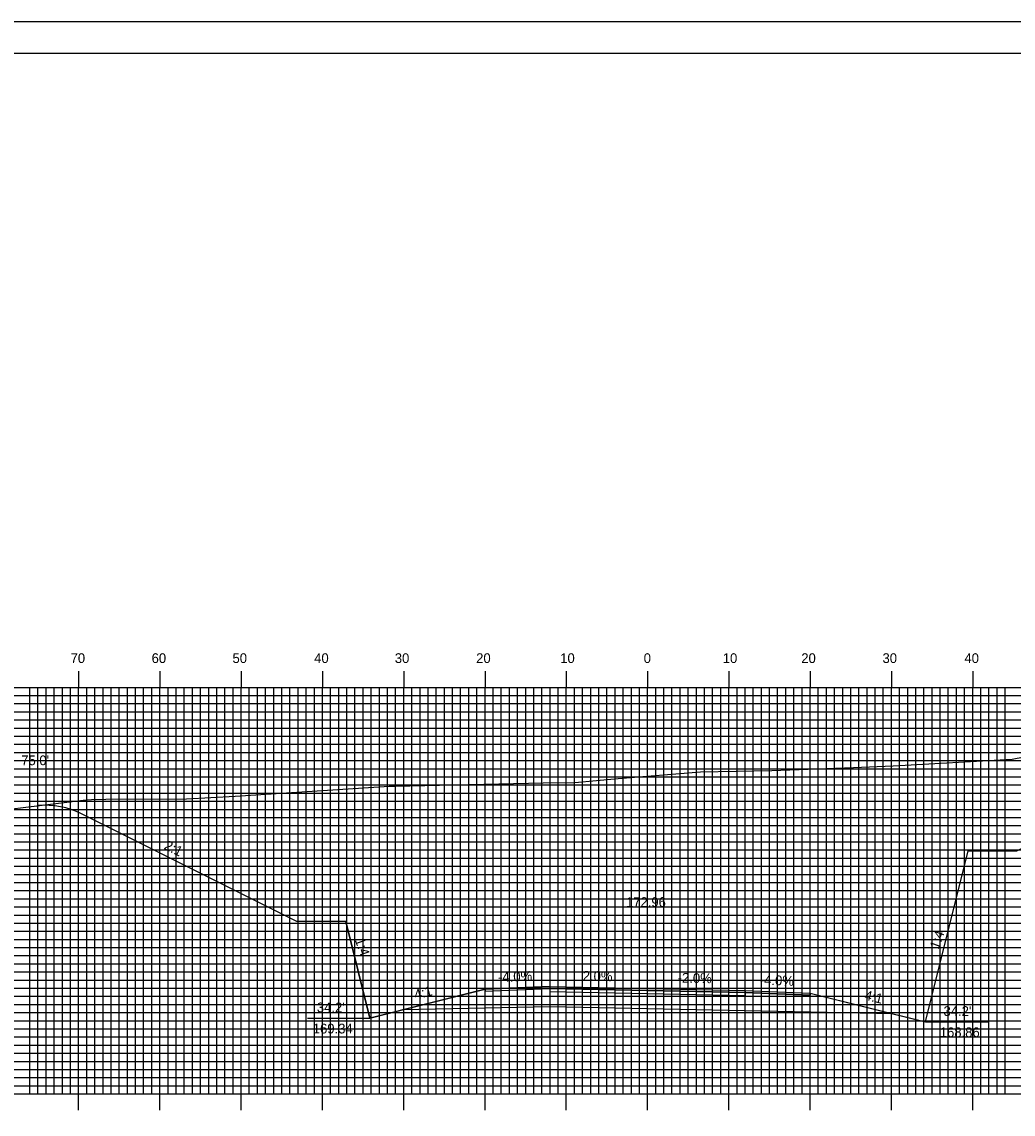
# Model space of a CAD drawing. Extents: x 1794846 to 1795189, y 442591 to 442811.
# Drawn here: x 1794934.9 to 1795056.8, y 442676.2 to 442810.5 of the extents above; entities that cross this region are included whole.
import ezdxf

# ---------------------------------------------------------------- set-up
doc = ezdxf.new("R2010")
doc.units = 0
for name, color, linetype in [('ANNOTATION', 7, 'Continuous'), ('BORDER', 7, 'Continuous'), ('D_Roadway_Centerline', 7, 'Continuous'), ('D_Roadway_Centerline_Text', 7, 'Continuous'), ('D_Roadway_Edge_Shoulder', 7, 'Continuous'), ('D_Roadway_Edge_TW', 7, 'Continuous'), ('D_Roadway_Pavement', 7, 'Continuous'), ('D_Roadway_SlopeLines', 7, 'Continuous'), ('D_Roadway_SubGrade', 7, 'Continuous'), ('D_Text_Standard', 7, 'Continuous'), ('H_V ANNOTATION', 7, 'Continuous'), ('MAJOR', 7, 'Continuous'), ('MINOR', 7, 'Continuous'), ('PDRAIN', 7, 'Continuous'), ('PLOT BOUNDARY', 7, 'Continuous'), ('S_Roadway_Centerline', 7, 'Continuous')]:
    doc.layers.add(name, color=color, linetype=linetype)

msp = doc.modelspace()

# ---------------------------------------------------------------- linework, layer by layer
at = {"layer": 'BORDER'}
msp.add_lwpolyline([(1794862.25, 442596.67), (1795182.25, 442596.67), (1795182.25, 442806.67), (1794862.25, 442806.67)], close=True, dxfattribs=at)
at = {"layer": 'D_Roadway_Centerline'}
msp.add_lwpolyline([(1794974.71, 442699.87), (1794977.68, 442688), (1794981.68, 442689), (1794991.85, 442691.55), (1794999.85, 442691.87), (1795011.85, 442691.63), (1795023.85, 442691.39), (1795031.85, 442691.07), (1795042.03, 442688.52), (1795046.03, 442687.52), (1795051.29, 442708.57), (1795057.29, 442708.57), (1795081.65, 442720.74)], dxfattribs=at)
msp.add_arc((1794937.74, 442704.17), 10, 63.4349, 95.1256, dxfattribs=at)
at = {"layer": 'D_Roadway_Edge_Shoulder'}
for points in [[(1794999.85, 442691.87), (1794991.85, 442691.55), (1794991.85, 442691.3), (1794999.85, 442691.62)], [(1795023.85, 442691.39), (1795031.85, 442691.07), (1795031.85, 442690.82), (1795023.85, 442691.14)]]:
    msp.add_lwpolyline(points, close=True, dxfattribs=at)
at = {"layer": 'D_Roadway_Edge_TW'}
msp.add_lwpolyline([(1794999.85, 442691.62), (1794999.85, 442691.87), (1795011.85, 442691.63), (1795023.85, 442691.39), (1795023.85, 442691.14), (1795011.85, 442691.38)], close=True, dxfattribs=at)
at = {"layer": 'D_Roadway_Pavement'}
msp.add_lwpolyline([(1794999.85, 442691.2), (1794999.85, 442691.62), (1795011.85, 442691.38), (1795023.85, 442691.14), (1795023.85, 442690.72), (1795011.85, 442690.96)], close=True, dxfattribs=at)
at = {"layer": 'D_Roadway_SlopeLines'}
for points in [[(1794974.71, 442699.87), (1794968.71, 442699.87), (1794942.22, 442713.11)], [(1794977.68, 442688), (1794974.71, 442699.87)], [(1794991.85, 442691.55), (1794977.68, 442688)], [(1795031.85, 442691.07), (1795046.03, 442687.52)]]:
    msp.add_lwpolyline(points, dxfattribs=at)
at = {"layer": 'D_Roadway_SubGrade'}
msp.add_lwpolyline([(1794999.85, 442689.37), (1794981.68, 442689), (1794991.85, 442691.55), (1794991.85, 442691.3), (1794999.85, 442691.62), (1795011.85, 442691.38), (1795023.85, 442691.14), (1795031.85, 442690.82), (1795031.85, 442691.07), (1795042.03, 442688.52), (1795023.85, 442688.89), (1795011.85, 442689.13)], close=True, dxfattribs=at)
at = {"layer": 'MAJOR'}
for p, q in [((1794941.85, 442730.67), (1794941.85, 442728.67)), ((1794951.85, 442730.67), (1794951.85, 442728.67)), ((1794961.85, 442730.67), (1794961.85, 442728.67)), ((1794971.85, 442730.67), (1794971.85, 442728.67)), ((1794981.85, 442730.67), (1794981.85, 442728.67)), ((1794991.85, 442730.67), (1794991.85, 442728.67)), ((1795001.85, 442730.67), (1795001.85, 442728.67)), ((1795011.85, 442730.67), (1795011.85, 442728.67)), ((1795021.85, 442730.67), (1795021.85, 442728.67)), ((1795031.85, 442730.67), (1795031.85, 442728.67)), ((1795041.85, 442730.67), (1795041.85, 442728.67)), ((1795051.85, 442730.67), (1795051.85, 442728.67)), ((1794871.85, 442728.67), (1795151.85, 442728.67)), ((1794871.85, 442728.67), (1795151.85, 442728.67)), ((1794941.85, 442678.67), (1794941.85, 442728.67)), ((1794951.85, 442678.67), (1794951.85, 442728.67)), ((1794961.85, 442678.67), (1794961.85, 442728.67)), ((1794971.85, 442678.67), (1794971.85, 442728.67)), ((1794981.85, 442678.67), (1794981.85, 442728.67)), ((1794991.85, 442678.67), (1794991.85, 442728.67)), ((1795001.85, 442678.67), (1795001.85, 442728.67)), ((1795011.85, 442678.67), (1795011.85, 442728.67)), ((1795021.85, 442678.67), (1795021.85, 442728.67)), ((1795031.85, 442678.67), (1795031.85, 442728.67)), ((1795041.85, 442678.67), (1795041.85, 442728.67)), ((1795051.85, 442678.67), (1795051.85, 442728.67)), ((1794871.85, 442723.67), (1795151.85, 442723.67)), ((1794871.85, 442718.67), (1795151.85, 442718.67)), ((1794871.85, 442713.67), (1795151.85, 442713.67)), ((1794871.85, 442708.67), (1795151.85, 442708.67)), ((1794871.85, 442703.67), (1795151.85, 442703.67)), ((1794871.85, 442698.67), (1795151.85, 442698.67)), ((1794871.85, 442693.67), (1795151.85, 442693.67)), ((1794871.85, 442688.67), (1795151.85, 442688.67)), ((1794871.85, 442683.67), (1795151.85, 442683.67)), ((1794871.85, 442678.67), (1795151.85, 442678.67)), ((1794871.85, 442678.67), (1795151.85, 442678.67)), ((1794941.85, 442676.66), (1794941.85, 442678.67)), ((1794951.85, 442676.66), (1794951.85, 442678.67)), ((1794961.85, 442676.66), (1794961.85, 442678.67)), ((1794971.85, 442676.66), (1794971.85, 442678.67)), ((1794981.85, 442676.66), (1794981.85, 442678.67)), ((1794991.85, 442676.66), (1794991.85, 442678.67)), ((1795001.85, 442676.66), (1795001.85, 442678.67)), ((1795011.85, 442676.66), (1795011.85, 442678.67)), ((1795021.85, 442676.66), (1795021.85, 442678.67)), ((1795031.85, 442676.66), (1795031.85, 442678.67)), ((1795041.85, 442676.66), (1795041.85, 442678.67)), ((1795051.85, 442676.66), (1795051.85, 442678.67))]:
    msp.add_line(p, q, dxfattribs=at)
at = {"layer": 'MINOR'}
for p, q in [((1794935.85, 442678.67), (1794935.85, 442728.67)), ((1794936.85, 442678.67), (1794936.85, 442728.67)), ((1794937.85, 442678.67), (1794937.85, 442728.67)), ((1794938.85, 442678.67), (1794938.85, 442728.67)), ((1794939.85, 442678.67), (1794939.85, 442728.67)), ((1794940.85, 442678.67), (1794940.85, 442728.67)), ((1794942.85, 442678.67), (1794942.85, 442728.67)), ((1794943.85, 442678.67), (1794943.85, 442728.67)), ((1794944.85, 442678.67), (1794944.85, 442728.67)), ((1794945.85, 442678.67), (1794945.85, 442728.67)), ((1794946.85, 442678.67), (1794946.85, 442728.67)), ((1794947.85, 442678.67), (1794947.85, 442728.67)), ((1794948.85, 442678.67), (1794948.85, 442728.67)), ((1794949.85, 442678.67), (1794949.85, 442728.67)), ((1794950.85, 442678.67), (1794950.85, 442728.67)), ((1794952.85, 442678.67), (1794952.85, 442728.67)), ((1794953.85, 442678.67), (1794953.85, 442728.67)), ((1794954.85, 442678.67), (1794954.85, 442728.67)), ((1794955.85, 442678.67), (1794955.85, 442728.67)), ((1794956.85, 442678.67), (1794956.85, 442728.67)), ((1794957.85, 442678.67), (1794957.85, 442728.67)), ((1794958.85, 442678.67), (1794958.85, 442728.67)), ((1794959.85, 442678.67), (1794959.85, 442728.67)), ((1794960.85, 442678.67), (1794960.85, 442728.67)), ((1794962.85, 442678.67), (1794962.85, 442728.67)), ((1794963.85, 442678.67), (1794963.85, 442728.67)), ((1794964.85, 442678.67), (1794964.85, 442728.67)), ((1794965.85, 442678.67), (1794965.85, 442728.67)), ((1794966.85, 442678.67), (1794966.85, 442728.67)), ((1794967.85, 442678.67), (1794967.85, 442728.67)), ((1794968.85, 442678.67), (1794968.85, 442728.67)), ((1794969.85, 442678.67), (1794969.85, 442728.67)), ((1794970.85, 442678.67), (1794970.85, 442728.67)), ((1794972.85, 442678.67), (1794972.85, 442728.67)), ((1794973.85, 442678.67), (1794973.85, 442728.67)), ((1794974.85, 442678.67), (1794974.85, 442728.67)), ((1794975.85, 442678.67), (1794975.85, 442728.67)), ((1794976.85, 442678.67), (1794976.85, 442728.67)), ((1794977.85, 442678.67), (1794977.85, 442728.67)), ((1794978.85, 442678.67), (1794978.85, 442728.67)), ((1794979.85, 442678.67), (1794979.85, 442728.67)), ((1794980.85, 442678.67), (1794980.85, 442728.67)), ((1794982.85, 442678.67), (1794982.85, 442728.67)), ((1794983.85, 442678.67), (1794983.85, 442728.67)), ((1794984.85, 442678.67), (1794984.85, 442728.67)), ((1794985.85, 442678.67), (1794985.85, 442728.67)), ((1794986.85, 442678.67), (1794986.85, 442728.67)), ((1794987.85, 442678.67), (1794987.85, 442728.67)), ((1794988.85, 442678.67), (1794988.85, 442728.67)), ((1794989.85, 442678.67), (1794989.85, 442728.67)), ((1794990.85, 442678.67), (1794990.85, 442728.67)), ((1794992.85, 442678.67), (1794992.85, 442728.67)), ((1794993.85, 442678.67), (1794993.85, 442728.67)), ((1794994.85, 442678.67), (1794994.85, 442728.67)), ((1794995.85, 442678.67), (1794995.85, 442728.67)), ((1794996.85, 442678.67), (1794996.85, 442728.67)), ((1794997.85, 442678.67), (1794997.85, 442728.67)), ((1794998.85, 442678.67), (1794998.85, 442728.67)), ((1794999.85, 442678.67), (1794999.85, 442728.67)), ((1795000.85, 442678.67), (1795000.85, 442728.67)), ((1795002.85, 442678.67), (1795002.85, 442728.67)), ((1795003.85, 442678.67), (1795003.85, 442728.67)), ((1795004.85, 442678.67), (1795004.85, 442728.67)), ((1795005.85, 442678.67), (1795005.85, 442728.67)), ((1795006.85, 442678.67), (1795006.85, 442728.67)), ((1795007.85, 442678.67), (1795007.85, 442728.67)), ((1795008.85, 442678.67), (1795008.85, 442728.67)), ((1795009.85, 442678.67), (1795009.85, 442728.67)), ((1795010.85, 442678.67), (1795010.85, 442728.67)), ((1795012.85, 442678.67), (1795012.85, 442728.67)), ((1795013.85, 442678.67), (1795013.85, 442728.67)), ((1795014.85, 442678.67), (1795014.85, 442728.67)), ((1795015.85, 442678.67), (1795015.85, 442728.67)), ((1795016.85, 442678.67), (1795016.85, 442728.67)), ((1795017.85, 442678.67), (1795017.85, 442728.67)), ((1795018.85, 442678.67), (1795018.85, 442728.67)), ((1795019.85, 442678.67), (1795019.85, 442728.67)), ((1795020.85, 442678.67), (1795020.85, 442728.67)), ((1795022.85, 442678.67), (1795022.85, 442728.67)), ((1795023.85, 442678.67), (1795023.85, 442728.67)), ((1795024.85, 442678.67), (1795024.85, 442728.67)), ((1795025.85, 442678.67), (1795025.85, 442728.67)), ((1795026.85, 442678.67), (1795026.85, 442728.67)), ((1795027.85, 442678.67), (1795027.85, 442728.67)), ((1795028.85, 442678.67), (1795028.85, 442728.67)), ((1795029.85, 442678.67), (1795029.85, 442728.67)), ((1795030.85, 442678.67), (1795030.85, 442728.67)), ((1795032.85, 442678.67), (1795032.85, 442728.67)), ((1795033.85, 442678.67), (1795033.85, 442728.67)), ((1795034.85, 442678.67), (1795034.85, 442728.67)), ((1795035.85, 442678.67), (1795035.85, 442728.67)), ((1795036.85, 442678.67), (1795036.85, 442728.67)), ((1795037.85, 442678.67), (1795037.85, 442728.67)), ((1795038.85, 442678.67), (1795038.85, 442728.67)), ((1795039.85, 442678.67), (1795039.85, 442728.67)), ((1795040.85, 442678.67), (1795040.85, 442728.67)), ((1795042.85, 442678.67), (1795042.85, 442728.67)), ((1795043.85, 442678.67), (1795043.85, 442728.67)), ((1795044.85, 442678.67), (1795044.85, 442728.67)), ((1795045.85, 442678.67), (1795045.85, 442728.67)), ((1795046.85, 442678.67), (1795046.85, 442728.67)), ((1795047.85, 442678.67), (1795047.85, 442728.67)), ((1795048.85, 442678.67), (1795048.85, 442728.67)), ((1795049.85, 442678.67), (1795049.85, 442728.67)), ((1795050.85, 442678.67), (1795050.85, 442728.67)), ((1795052.85, 442678.67), (1795052.85, 442728.67)), ((1795053.85, 442678.67), (1795053.85, 442728.67)), ((1795054.85, 442678.67), (1795054.85, 442728.67)), ((1795055.85, 442678.67), (1795055.85, 442728.67)), ((1794871.85, 442727.67), (1795151.85, 442727.67)), ((1794871.85, 442726.67), (1795151.85, 442726.67)), ((1794871.85, 442725.67), (1795151.85, 442725.67)), ((1794871.85, 442724.67), (1795151.85, 442724.67)), ((1794871.85, 442722.67), (1795151.85, 442722.67)), ((1794871.85, 442721.67), (1795151.85, 442721.67)), ((1794871.85, 442720.67), (1795151.85, 442720.67)), ((1794871.85, 442719.67), (1795151.85, 442719.67)), ((1794871.85, 442717.67), (1795151.85, 442717.67)), ((1794871.85, 442716.67), (1795151.85, 442716.67)), ((1794871.85, 442715.67), (1795151.85, 442715.67)), ((1794871.85, 442714.67), (1795151.85, 442714.67)), ((1794871.85, 442712.67), (1795151.85, 442712.67)), ((1794871.85, 442711.67), (1795151.85, 442711.67)), ((1794871.85, 442710.67), (1795151.85, 442710.67)), ((1794871.85, 442709.67), (1795151.85, 442709.67)), ((1794871.85, 442707.67), (1795151.85, 442707.67)), ((1794871.85, 442706.67), (1795151.85, 442706.67)), ((1794871.85, 442705.67), (1795151.85, 442705.67)), ((1794871.85, 442704.67), (1795151.85, 442704.67)), ((1794871.85, 442702.67), (1795151.85, 442702.67)), ((1794871.85, 442701.67), (1795151.85, 442701.67)), ((1794871.85, 442700.67), (1795151.85, 442700.67)), ((1794871.85, 442699.67), (1795151.85, 442699.67)), ((1794871.85, 442697.67), (1795151.85, 442697.67)), ((1794871.85, 442696.67), (1795151.85, 442696.67)), ((1794871.85, 442695.67), (1795151.85, 442695.67)), ((1794871.85, 442694.67), (1795151.85, 442694.67)), ((1794871.85, 442692.67), (1795151.85, 442692.67)), ((1794871.85, 442691.67), (1795151.85, 442691.67)), ((1794871.85, 442690.67), (1795151.85, 442690.67)), ((1794871.85, 442689.67), (1795151.85, 442689.67)), ((1794871.85, 442687.67), (1795151.85, 442687.67)), ((1794871.85, 442686.67), (1795151.85, 442686.67)), ((1794871.85, 442685.67), (1795151.85, 442685.67)), ((1794871.85, 442684.67), (1795151.85, 442684.67)), ((1794871.85, 442682.67), (1795151.85, 442682.67)), ((1794871.85, 442681.67), (1795151.85, 442681.67)), ((1794871.85, 442680.67), (1795151.85, 442680.67)), ((1794871.85, 442679.67), (1795151.85, 442679.67))]:
    msp.add_line(p, q, dxfattribs=at)
at = {"layer": 'PDRAIN'}
for p, q in [((1794970, 442688), (1794977.68, 442688)), ((1795046.03, 442687.52), (1795053.72, 442687.52))]:
    msp.add_line(p, q, dxfattribs=at)
at = {"layer": 'PLOT BOUNDARY'}
msp.add_lwpolyline([(1794846.07, 442590.55), (1795186.07, 442590.55), (1795186.07, 442810.55), (1794846.07, 442810.55)], close=True, dxfattribs=at)
at = {"layer": 'S_Roadway_Centerline'}
msp.add_lwpolyline([(1794931.62, 442713.49), (1794942.42, 442714.81), (1794943.45, 442714.89), (1794945.21, 442714.92), (1794955.12, 442714.95), (1794961.11, 442715.28), (1794980.06, 442716.51), (1794980.18, 442716.52), (1794980.78, 442716.52), (1794999, 442716.93), (1795002.88, 442716.98), (1795008.21, 442717.47), (1795018.35, 442718.27), (1795027.14, 442718.43), (1795037.17, 442718.81), (1795042.05, 442719.03), (1795056.72, 442719.86), (1795058.16, 442720.13)], dxfattribs=at)

# ---------------------------------------------------------------- texts
at = {"layer": 'ANNOTATION'}
for s, rotation, p in [('2:1', 333.4349, (1794952.27, 442708.84)), ('2:1', 333.4349, (1794952.27, 442708.84)), ('1:4', 289.484, (1794975.82, 442697.61)), ('1:4', 70.516, (1795047.66, 442696.38)), ('-4.0%', 2.2906, (1794993.48, 442692.42)), ('2.0%', 358.8542, (1795003.86, 442692.59)), ('-2.0%', 358.8542, (1795015.54, 442692.36)), ('-4.0%', 357.7094, (1795025.64, 442692.12)), ('4:1', 14.0362, (1794983.3, 442690.27)), ('4:1', 345.9638, (1795038.45, 442690.28))]:
    msp.add_text(s, height=1.2, rotation=rotation, dxfattribs=at).set_placement(p)
for s, p in [("34.2'", (1794971.16, 442688.7)), ("34.2'", (1795048.26, 442688.25)), ('169.34', (1794970.66, 442686.1)), ('168.86', (1795047.8, 442685.65))]:
    msp.add_text(s, height=1.2, dxfattribs=at).set_placement(p)
at = {"layer": 'D_Roadway_Centerline'}
for s, p in [('C', (1795011.85, 442691.63)), ('L', (1795011.85, 442691.62))]:
    msp.add_text(s, height=0.0146, dxfattribs=at).set_placement(p)
at = {"layer": 'D_Roadway_Centerline_Text'}
msp.add_text('172.96', height=1.2, dxfattribs=at).set_placement((1795009.19, 442701.66))
at = {"layer": 'D_Text_Standard'}
msp.add_text("75.0'", height=1.2, dxfattribs=at).set_placement((1794934.79, 442719.1))
at = {"layer": 'H_V ANNOTATION'}
for s, p in [('70', (1794940.86, 442731.67)), ('60', (1794950.83, 442731.67)), ('50', (1794960.78, 442731.67)), ('40', (1794970.83, 442731.67)), ('30', (1794980.75, 442731.67)), ('20', (1794990.76, 442731.67)), ('10', (1795001.1, 442731.67)), ('0', (1795011.37, 442731.67)), ('10', (1795021.1, 442731.67)), ('20', (1795030.76, 442731.67)), ('30', (1795040.75, 442731.67)), ('40', (1795050.83, 442731.67))]:
    msp.add_text(s, height=1.2, dxfattribs=at).set_placement(p)

doc.saveas('drawing.dxf')
